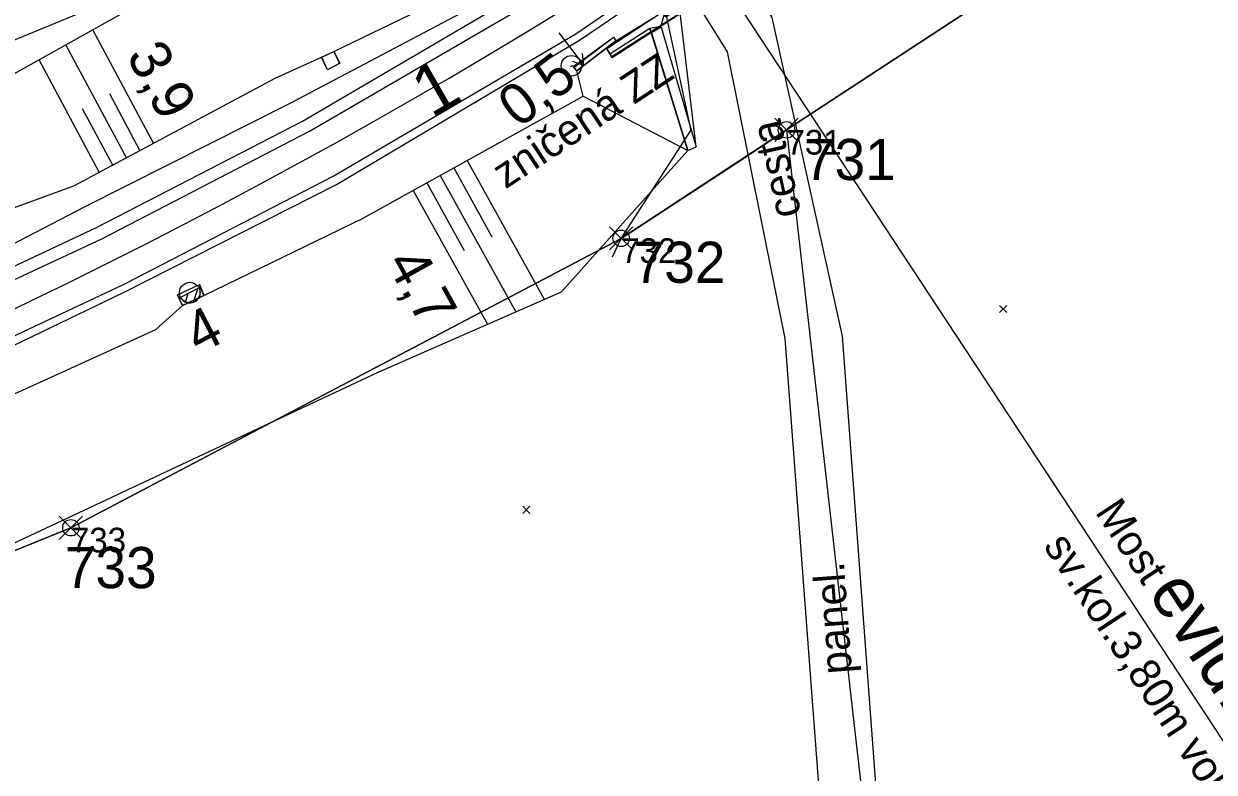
# Model space of a CAD drawing. Extents: x -800194 to -799078, y -1007177 to -1006597.
# Drawn here: x -799524.3 to -799466.4, y -1006989.7 to -1006953.3 of the extents above; entities that cross this region are included whole.
import ezdxf

# ---------------------------------------------------------------- set-up
doc = ezdxf.new("R2010")
doc.units = 0
for name, color, linetype in [('02_Osa_koleje', 7, 'Continuous'), ('Obvod stavby', 7, 'Continuous'), ('Vrstva 1', 7, 'Continuous'), ('Vrstva 11', 7, 'Continuous'), ('Vrstva 12', 7, 'Continuous'), ('Vrstva 13', 7, 'Continuous'), ('Vrstva 17', 7, 'Continuous'), ('Vrstva 18', 7, 'Continuous'), ('Vrstva 4', 7, 'Continuous'), ('Vrstva 48', 7, 'Continuous'), ('Vrstva 49', 7, 'Continuous'), ('Vrstva 50', 7, 'Continuous'), ('Vrstva 51', 7, 'Continuous'), ('Vrstva 53', 7, 'Continuous'), ('Vrstva 55', 7, 'Continuous'), ('Vrstva 56', 7, 'Continuous'), ('Vrstva 60', 7, 'Continuous')]:
    doc.layers.add(name, color=color, linetype=linetype)

msp = doc.modelspace()

# ---------------------------------------------------------------- linework, layer by layer
at = {"layer": '02_Osa_koleje'}
msp.add_arc((-799651.022, -1006703.891), 292, 255.62486, 308.20516, dxfattribs=at)
at = {"layer": 'Obvod stavby'}
for p, q in [((-799487.786, -1006959.036), (-799486.654, -1006957.904)), ((-799487.786, -1006957.904), (-799486.654, -1006959.036)), ((-799495.816, -1006964.306), (-799494.684, -1006963.174)), ((-799495.816, -1006963.174), (-799494.684, -1006964.306)), ((-799522.546, -1006978.366), (-799521.414, -1006977.234)), ((-799522.546, -1006977.234), (-799521.414, -1006978.366))]:
    msp.add_line(p, q, dxfattribs=at)
msp.add_lwpolyline([(-799559.64, -1006968.48), (-799519.68, -1006952.01), (-799500.87, -1006940.41), (-799496.64, -1006937.8), (-799494.85, -1006936.7), (-799484.52, -1006930.32), (-799457.99, -1006908.8), (-799435, -1006885.17), (-799430.26, -1006880.27), (-799425.53, -1006875.38), (-799422.55, -1006864.36), (-799416.748, -1006858.798), (-799395.763, -1006879.374), (-799413.75, -1006898.23), (-799418.41, -1006902.53), (-799423.07, -1006906.83), (-799433.4, -1006916.39), (-799469.5, -1006946.86), (-799487.22, -1006958.47), (-799495.25, -1006963.74), (-799521.98, -1006977.8), (-799546.71, -1006987.83)], dxfattribs=at)
for centre in [(-799487.22, -1006958.47), (-799495.25, -1006963.74), (-799521.98, -1006977.8)]:
    msp.add_circle(centre, 0.4, dxfattribs=at)
at = {"layer": 'Vrstva 11'}
for p, q in [((-799515.756, -1006966.147), (-799516.65, -1006966.611)), ((-799516.03, -1006966.85), (-799515.818, -1006966.179)), ((-799516.417, -1006966.83), (-799516.288, -1006966.423))]:
    msp.add_line(p, q, dxfattribs=at)
msp.add_circle((-799516.203, -1006966.379), 0.503, dxfattribs=at)
msp.add_arc((-799516.203, -1006966.379), 0.503, 207.40956, 27.40956, dxfattribs=at)
at = {"layer": 'Vrstva 12'}
for p, q in [((-799509.205, -1006954.66), (-799509.204, -1006954.659)), ((-799509.8, -1006954.937), (-799509.799, -1006954.938)), ((-799508.927, -1006955.239), (-799508.921, -1006955.236)), ((-799509.513, -1006955.55), (-799509.519, -1006955.553))]:
    msp.add_line(p, q, dxfattribs=at)
for points in [[(-799509.8, -1006954.937), (-799509.204, -1006954.659), (-799508.921, -1006955.236), (-799509.519, -1006955.553), (-799509.8, -1006954.937)], [(-799509.799, -1006954.938), (-799509.205, -1006954.66), (-799508.927, -1006955.239), (-799509.513, -1006955.55), (-799509.799, -1006954.938)], [(-799516.805, -1006966.486), (-799515.734, -1006965.976), (-799515.522, -1006966.509), (-799516.557, -1006966.998), (-799516.805, -1006966.486)], [(-799516.805, -1006966.486), (-799516.556, -1006966.997), (-799515.527, -1006966.511), (-799515.734, -1006965.976)], [(-799515.527, -1006966.511), (-799515.522, -1006966.509)], [(-799516.557, -1006966.998), (-799516.556, -1006966.997)]]:
    msp.add_lwpolyline(points, dxfattribs=at)
at = {"layer": 'Vrstva 13'}
msp.add_line((-799498.282, -1006953.755), (-799497.066, -1006955.343), dxfattribs=at)
for points in [[(-799497.585, -1006955.395), (-799495.628, -1006953.965), (-799495.505, -1006954.146)], [(-799497.535, -1006955.431), (-799495.628, -1006953.965), (-799495.506, -1006954.147), (-799497.399, -1006955.598), (-799497.535, -1006955.431)], [(-799495.506, -1006954.147), (-799495.505, -1006954.146), (-799497.4, -1006955.599), (-799497.399, -1006955.598)], [(-799497.608, -1006955.128), (-799497.066, -1006955.343), (-799497.132, -1006954.763)], [(-799497.4, -1006955.599), (-799497.585, -1006955.395), (-799497.535, -1006955.431)]]:
    msp.add_lwpolyline(points, dxfattribs=at)
at = {"layer": 'Vrstva 17'}
msp.add_lwpolyline([(-799495.74, -1006954.93), (-799493.422, -1006953.452), (-799487.055, -1006949.386), (-799484.733, -1006947.883)], dxfattribs=at)
at = {"layer": 'Vrstva 18'}
for p, q in [((-799458.168, -1007000.066), (-799490.201, -1006951.402)), ((-799493.105, -1006952.61), (-799493.33, -1006953.427)), ((-799493.856, -1006953.526), (-799492.007, -1006959.466)), ((-799493.786, -1006953.752), (-799493.856, -1006953.526)), ((-799493.314, -1006953.482), (-799493.33, -1006953.427)), ((-799493.314, -1006953.482), (-799491.611, -1006959.287)), ((-799493.786, -1006953.752), (-799492.007, -1006959.466))]:
    msp.add_line(p, q, dxfattribs=at)
for points in [[(-799485.016, -1006947.459), (-799487.565, -1006949.124), (-799487.499, -1006949.378), (-799493.081, -1006952.976), (-799493.236, -1006952.753), (-799495.947, -1006954.533), (-799495.696, -1006954.958), (-799484.706, -1006947.846)], [(-799484.706, -1006947.846), (-799487.208, -1006949.465), (-799493.33, -1006953.427), (-799495.696, -1006954.958), (-799495.696, -1006954.958)], [(-799492.007, -1006959.466), (-799491.611, -1006959.287), (-799492.448, -1006952.232), (-799493.155, -1006952.694)], [(-799495.8, -1006954.78), (-799493.856, -1006953.526), (-799493.856, -1006953.526)], [(-799495.799, -1006954.779), (-799493.856, -1006953.526), (-799493.33, -1006953.427)], [(-799493.314, -1006953.482), (-799493.786, -1006953.752)], [(-799495.696, -1006954.958), (-799495.799, -1006954.779), (-799495.8, -1006954.78), (-799495.949, -1006954.534), (-799495.947, -1006954.533)]]:
    msp.add_lwpolyline(points, dxfattribs=at)
at = {"layer": 'Vrstva 4'}
for points in [[(-799510.394, -1006958.536), (-799498.027, -1006951.328), (-799477.988, -1006937.435), (-799460.33, -1006923.117), (-799451.862, -1006915.581), (-799443.604, -1006907.9), (-799435.444, -1006900.067), (-799428.64, -1006893.299), (-799422.817, -1006887.511), (-799415.998, -1006880.595), (-799408.158, -1006872.652), (-799401.02, -1006864.85)], [(-799509.248, -1006960.724), (-799497.456, -1006953.809), (-799476.495, -1006939.437), (-799458.707, -1006924.982), (-799450.277, -1006917.43), (-799441.932, -1006909.717), (-799433.783, -1006901.867), (-799426.9, -1006895.092), (-799421.037, -1006889.182), (-799414.218, -1006882.281), (-799406.443, -1006874.417), (-799398.609, -1006866.93)], [(-799511.236, -1006957.129), (-799499.236, -1006950.771), (-799498.598, -1006949.914), (-799498.679, -1006949.705), (-799496.151, -1006948.479), (-799496.251, -1006948.258), (-799490.687, -1006944.683), (-799490.497, -1006944.878), (-799488.249, -1006943.052), (-799488.105, -1006943.216), (-799486.269, -1006941.68), (-799478.997, -1006936.484), (-799474.568, -1006932.916), (-799474.237, -1006932.694), (-799461.519, -1006921.99), (-799452.935, -1006914.372), (-799444.695, -1006906.886), (-799436.579, -1006898.932), (-799429.629, -1006892.192), (-799429.07, -1006892.727), (-799423.479, -1006886.901), (-799416.56, -1006880.007), (-799417.085, -1006879.46), (-799415.349, -1006878.386)], [(-799510.726, -1006958.045), (-799497.901, -1006950.516), (-799478.36, -1006937.055), (-799461.534, -1006923.53), (-799452.128, -1006915.305), (-799443.894, -1006907.632), (-799435.739, -1006899.754), (-799428.922, -1006893.007), (-799423.223, -1006887.256), (-799416.277, -1006880.269), (-799414.896, -1006878.87)], [(-799509.087, -1006961.127), (-799497.277, -1006954.118), (-799476.183, -1006939.802), (-799458.586, -1006925.284), (-799449.914, -1006917.869), (-799441.499, -1006910.139), (-799433.371, -1006902.28), (-799426.451, -1006895.478), (-799420.657, -1006889.585), (-799413.85, -1006882.742), (-799412.388, -1006881.287)], [(-799507.817, -1006962.779), (-799497.104, -1006956.83), (-799497.4, -1006955.599), (-799497.585, -1006955.395), (-799495.628, -1006953.965), (-799495.505, -1006954.146), (-799493.236, -1006952.753), (-799493.081, -1006952.976), (-799487.499, -1006949.378), (-799487.565, -1006949.124), (-799485.713, -1006947.881), (-799485.847, -1006947.698), (-799483.858, -1006946.36), (-799483.734, -1006946.536), (-799483.686, -1006946.569), (-799482.647, -1006946.068), (-799475.489, -1006940.774), (-799457.684, -1006926.366)], [(-799766.319, -1006970.565), (-799760.949, -1006972.542), (-799747.638, -1006977.46), (-799730.549, -1006982.982), (-799710.066, -1006987.578), (-799704.728, -1006988.346), (-799693.001, -1006990.373), (-799682.434, -1006991.64), (-799671.27, -1006992.619), (-799659.31, -1006993.026), (-799648.69, -1006993.125), (-799637.398, -1006992.704), (-799625.913, -1006992.175), (-799614.965, -1006990.831), (-799603.911, -1006989.312), (-799592.728, -1006987.172), (-799581.605, -1006984.547), (-799570.583, -1006981.598), (-799559.909, -1006978.216), (-799542.956, -1006972.25), (-799531.79, -1006967.658), (-799521.285, -1006962.191), (-799511.236, -1006957.129)], [(-799531.454, -1006968.25), (-799520.744, -1006963.214), (-799510.726, -1006958.045)], [(-799779.678, -1006964.304), (-799766.319, -1006970.565), (-799761.253, -1006973.176), (-799747.77, -1006978.421), (-799730.774, -1006983.8), (-799710.333, -1006988.709), (-799704.916, -1006989.741), (-799693.131, -1006991.407), (-799682.585, -1006992.929), (-799671.325, -1006993.879), (-799659.363, -1006994.45), (-799648.66, -1006994.501), (-799637.23, -1006994.127), (-799626.066, -1006993.335), (-799614.788, -1006992.17), (-799603.669, -1006990.506), (-799592.467, -1006988.452), (-799581.281, -1006985.916), (-799570.22, -1006982.998), (-799559.296, -1006979.606), (-799542.375, -1006973.485), (-799531.236, -1006968.774), (-799520.48, -1006963.762), (-799510.394, -1006958.536)], [(-799776.864, -1006969.085), (-799770.965, -1006971.646), (-799761.91, -1006975.649), (-799748.544, -1006980.777), (-799731.457, -1006986.215), (-799711.132, -1006991.054), (-799705.482, -1006992.16), (-799693.53, -1006994.084), (-799682.801, -1006995.384), (-799671.514, -1006996.319), (-799659.449, -1006996.851), (-799648.588, -1006996.949), (-799637.262, -1006996.573), (-799625.835, -1006995.773), (-799614.546, -1006994.586), (-799603.199, -1006992.945), (-799591.969, -1006990.857), (-799580.647, -1006988.335), (-799569.534, -1006985.311), (-799558.557, -1006981.947), (-799541.405, -1006975.739), (-799530.263, -1006971.071), (-799519.455, -1006966), (-799509.248, -1006960.724)], [(-799776.864, -1006969.085), (-799771.262, -1006971.982), (-799762.131, -1006976.093), (-799748.706, -1006981.286), (-799731.51, -1006986.353), (-799711.222, -1006991.459), (-799705.527, -1006992.587), (-799693.582, -1006994.543), (-799682.85, -1006995.904), (-799671.5, -1006996.805), (-799659.556, -1006997.356), (-799648.616, -1006997.341), (-799637.276, -1006997.071), (-799625.828, -1006996.297), (-799614.43, -1006995.109), (-799603.18, -1006993.475), (-799591.849, -1006991.264), (-799580.564, -1006988.698), (-799569.449, -1006985.746), (-799558.385, -1006982.386), (-799541.268, -1006976.227), (-799530.102, -1006971.505), (-799519.398, -1006966.36), (-799509.087, -1006961.127)], [(-799529.217, -1006973.339), (-799517.856, -1006968.167), (-799516.556, -1006966.997), (-799515.527, -1006966.511), (-799507.817, -1006962.779)]]:
    msp.add_lwpolyline(points, dxfattribs=at)
at = {"layer": 'Vrstva 48'}
for p, q in [((-799517.964, -1006959.118), (-799520.911, -1006953.609)), ((-799519.286, -1006959.826), (-799522.22, -1006954.342)), ((-799520.609, -1006960.533), (-799523.529, -1006955.075)), ((-799518.625, -1006959.472), (-799520.095, -1006956.724)), ((-799519.947, -1006960.18), (-799521.411, -1006957.444)), ((-799503.387, -1006960.319), (-799501.531, -1006963.662)), ((-799502.731, -1006959.955), (-799498.984, -1006966.702)), ((-799504.698, -1006961.047), (-799502.876, -1006964.329)), ((-799504.043, -1006960.683), (-799500.364, -1006967.308)), ((-799505.354, -1006961.411), (-799501.743, -1006967.914))]:
    msp.add_line(p, q, dxfattribs=at)
at = {"layer": 'Vrstva 49'}
for p, q in [((-799497.104, -1006956.83), (-799492.007, -1006959.466)), ((-799476.879, -1006966.995), (-799476.525, -1006967.349)), ((-799476.879, -1006967.349), (-799476.525, -1006966.995)), ((-799500.036, -1006976.752), (-799499.682, -1006977.106)), ((-799500.036, -1006977.106), (-799499.682, -1006976.752))]:
    msp.add_line(p, q, dxfattribs=at)
for points in [[(-799510.22, -1006947.622), (-799525.177, -1006955.998), (-799527.677, -1006951.163), (-799532.773, -1006952.141), (-799538.673, -1006961.225), (-799541.203, -1006964.827)], [(-799512.053, -1006955.956), (-799509.8, -1006954.937), (-799509.204, -1006954.659), (-799500.879, -1006950.629), (-799498.679, -1006949.705), (-799499.015, -1006949.821), (-799499.13, -1006949.555), (-799496.989, -1006948.551)], [(-799507.817, -1006962.779), (-799497.104, -1006956.83), (-799497.4, -1006955.599), (-799495.505, -1006954.146), (-799495.949, -1006954.534), (-799495.8, -1006954.78), (-799493.856, -1006953.526)], [(-799507.056, -1006970.247), (-799498.146, -1006966.334), (-799492.007, -1006959.466), (-799493.856, -1006953.526)], [(-799532.47, -1006962.935), (-799529.843, -1006964.108), (-799521.836, -1006961.19), (-799512.053, -1006955.956)], [(-799710.319, -1006994.817), (-799708.871, -1006995.032), (-799692.771, -1006997.819), (-799673.296, -1007001.049), (-799659.562, -1007000.479), (-799648.457, -1007000.689), (-799625.451, -1006999.097), (-799615.697, -1006997.513), (-799614.57, -1006997.347), (-799602.963, -1006995.575), (-799579.498, -1006991.091), (-799558.66, -1006984.762), (-799544.861, -1006980.115), (-799538.187, -1006977.215), (-799529.217, -1006973.339), (-799517.856, -1006968.167), (-799516.556, -1006966.997), (-799515.527, -1006966.511), (-799507.817, -1006962.779)], [(-799641.812, -1007006.94), (-799620.997, -1007006.237), (-799608.683, -1007003.516), (-799602.423, -1007004.973), (-799584.286, -1006998.849), (-799562.538, -1006993.683), (-799545.397, -1006986.651), (-799532.459, -1006982.152), (-799507.056, -1006970.247)]]:
    msp.add_lwpolyline(points, dxfattribs=at)
at = {"layer": 'Vrstva 50'}
msp.add_line((-799497.709, -1006955.385), (-799497.623, -1006955.333), dxfattribs=at)
msp.add_circle((-799497.666, -1006955.359), 0.5, dxfattribs=at)
at = {"layer": 'Vrstva 51'}
for points in [[(-799487.284, -1006968.607), (-799490.087, -1006954.678), (-799499.499, -1006939.61), (-799503.236, -1006928.194), (-799504.313, -1006911.364)], [(-799484.495, -1006968.489), (-799487.918, -1006953.016), (-799496.949, -1006937.979), (-799500.5, -1006927.768), (-799500.929, -1006911.492)], [(-799485.172, -1006996.711), (-799487.284, -1006968.607)], [(-799482.419, -1006996.557), (-799484.495, -1006968.489)]]:
    msp.add_lwpolyline(points, dxfattribs=at)
at = {"layer": 'Vrstva 53'}
for points in [[(-799559.64, -1006968.48), (-799519.68, -1006952.01), (-799500.87, -1006940.41), (-799496.64, -1006937.8), (-799494.85, -1006936.7), (-799484.519, -1006930.319), (-799457.99, -1006908.8), (-799435, -1006885.17), (-799430.26, -1006880.27), (-799425.53, -1006875.38), (-799422.55, -1006864.36), (-799390.88, -1006834), (-799358.35, -1006806.65), (-799352.29, -1006801.56), (-799330.91, -1006783.58), (-799314.235, -1006766.649)], [(-799312.398, -1006791.976), (-799331.37, -1006811.87), (-799413.75, -1006898.23), (-799418.41, -1006902.53), (-799423.07, -1006906.83), (-799433.4, -1006916.39), (-799469.5, -1006946.86), (-799487.22, -1006958.47), (-799495.25, -1006963.74), (-799521.98, -1006977.8), (-799546.71, -1006987.83)]]:
    msp.add_lwpolyline(points, dxfattribs=at)
at = {"layer": 'Vrstva 55'}
msp.add_line((-799487.22, -1006958.47), (-799478.14, -1007038.23), dxfattribs=at)
for points in [[(-799487.22, -1006958.47), (-799469.5, -1006946.86), (-799433.4, -1006916.39)], [(-799667.43, -1006981.06), (-799637.16, -1006982.06), (-799603.07, -1006978.39), (-799559.64, -1006968.48), (-799519.68, -1006952.01)], [(-799599.63, -1007001.65), (-799583.97, -1006998.26), (-799572.22, -1006995.8), (-799546.71, -1006987.83), (-799521.98, -1006977.8), (-799495.25, -1006963.74), (-799489.22, -1006959.79), (-799487.22, -1006958.47)]]:
    msp.add_lwpolyline(points, dxfattribs=at)
at = {"layer": 'Vrstva 56'}
for p, q in [((-799493.13, -1006952.62), (-799491.86, -1006958.5)), ((-799495.25, -1006963.74), (-799491.86, -1006958.5)), ((-799495.673, -1006964.646), (-799495.251, -1006963.74))]:
    msp.add_line(p, q, dxfattribs=at)
at = {"layer": 'Vrstva 60'}
for p, q in [((-799487.22, -1006958.47), (-799487.22, -1006958.47)), ((-799495.25, -1006963.74), (-799495.25, -1006963.74)), ((-799521.98, -1006977.8), (-799521.98, -1006977.8))]:
    msp.add_line(p, q, dxfattribs=at)

# ---------------------------------------------------------------- texts
at = {"layer": 'Obvod stavby'}
for s, p in [('731', (-799486.373, -1006960.907)), ('732', (-799494.648, -1006965.902)), ('733', (-799522.278, -1006980.734))]:
    msp.add_text(s, height=2, rotation=360, dxfattribs=at).set_placement(p)
at = {"layer": 'Vrstva 1'}
msp.add_text('1', height=2.5, rotation=29.90367, dxfattribs=at).set_placement((-799504.461, -1006957.951))
at = {"layer": 'Vrstva 11'}
msp.add_text('4', height=2, rotation=27.40956, dxfattribs=at).set_placement((-799515.776, -1006969.401))
at = {"layer": 'Vrstva 13'}
msp.add_text('0,5', height=2, rotation=37.47046, dxfattribs=at).set_placement((-799500.234, -1006958.432))
at = {"layer": 'Vrstva 18'}
for s, height, p in [('Most', 1.5, (-799472.261, -1006977.035)), ('sv.kol.3,80m vol.v.5,00m', 1.5, (-799474.767, -1006978.685)), ('evid. km 204,470', 2.5, (-799469.707, -1006980.948))]:
    msp.add_text(s, height=height, rotation=303.35536, dxfattribs=at).set_placement(p)
at = {"layer": 'Vrstva 48'}
for s, rotation, p in [('3,9', 298.14721, (-799519.314, -1006954.859)), ('4,7', 299.0437, (-799506.697, -1006964.934))]:
    msp.add_text(s, height=2, rotation=rotation, dxfattribs=at).set_placement(p)
at = {"layer": 'Vrstva 50'}
msp.add_text('zničená ZZ', height=1.5, rotation=33.35536, dxfattribs=at).set_placement((-799500.873, -1006961.369))
at = {"layer": 'Vrstva 51'}
for s, rotation, p in [('cesta', 102.4743, (-799486.491, -1006962.568)), ('panel.', 94.23008, (-799484.033, -1006984.863))]:
    msp.add_text(s, height=1.5, rotation=rotation, dxfattribs=at).set_placement(p)
at = {"layer": 'Vrstva 60'}
for s, p in [('731', (-799487.22, -1006959.67)), ('732', (-799495.25, -1006964.94)), ('733', (-799521.98, -1006979))]:
    msp.add_text(s, height=1.2, dxfattribs=at).set_placement(p)

doc.saveas('drawing.dxf')
